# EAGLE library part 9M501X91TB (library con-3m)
CONNECTOR PCMCIA-CompactFlash
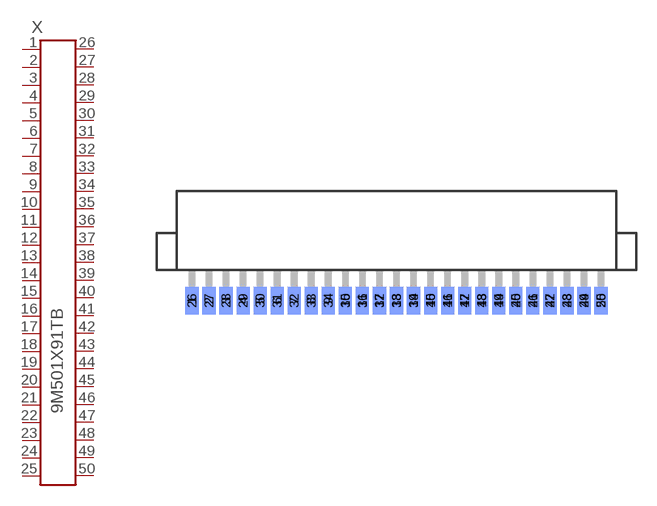
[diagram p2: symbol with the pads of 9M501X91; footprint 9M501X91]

Designator prefix X

## 9M501X91TB (OC_FARNELL: unknown; OC_NEWARK: unknown)  [9M501X91]
1  1  pas
2  2  pas
3  3  pas
4  4  pas
5  5  pas
6  6  pas
7  7  pas
8  8  pas
9  9  pas
10  10  pas
11  11  pas
12  12  pas
13  13  pas
14  14  pas
15  15  pas
16  16  pas
17  17  pas
18  18  pas
19  19  pas
20  20  pas
21  21  pas
22  22  pas
23  23  pas
24  24  pas
25  25  pas
26  26  pas
27  27  pas
28  28  pas
29  29  pas
30  30  pas
31  31  pas
32  32  pas
33  33  pas
34  34  pas
35  35  pas
36  36  pas
37  37  pas
38  38  pas
39  39  pas
40  40  pas
41  41  pas
42  42  pas
43  43  pas
44  44  pas
45  45  pas
46  46  pas
47  47  pas
48  48  pas
49  49  pas
50  50  pas

## Footprint 9M501X91 (pad centres in mm)
CONNECTOR PCMCIA-CompactFlash
smd 0.98 x 2.03: 1 -15.24,-3.29; 2 -13.97,-3.29; 3 -12.7,-3.29; 4 -11.43,-3.29; 5 -10.16,-3.29; 6 -8.89,-3.29; 7 -7.62,-3.29; 8 -6.35,-3.29; 9 -5.08,-3.29; 10 -3.81,-3.29; 11 -2.54,-3.29; 12 -1.27,-3.29; 13 0,-3.29; 14 1.27,-3.29; 15 2.54,-3.29; 16 3.81,-3.29; 17 5.08,-3.29; 18 6.35,-3.29; 19 7.62,-3.29; 20 8.89,-3.29; 21 10.16,-3.29; 22 11.43,-3.29; 23 12.7,-3.29; 24 13.97,-3.29; 25 15.24,-3.29
smd 0.98 x 2.03 bottom: 26 -15.24,-3.29; 27 -13.97,-3.29; 28 -12.7,-3.29; 29 -11.43,-3.29; 30 -10.16,-3.29; 31 -8.89,-3.29; 32 -7.62,-3.29; 33 -6.35,-3.29; 34 -5.08,-3.29; 35 -3.81,-3.29; 36 -2.54,-3.29; 37 -1.27,-3.29; 38 0,-3.29; 39 1.27,-3.29; 40 2.54,-3.29; 41 3.81,-3.29; 42 5.08,-3.29; 43 6.35,-3.29; 44 7.62,-3.29; 45 8.89,-3.29; 46 10.16,-3.29; 47 11.43,-3.29; 48 12.7,-3.29; 49 13.97,-3.29; 50 15.24,-3.29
